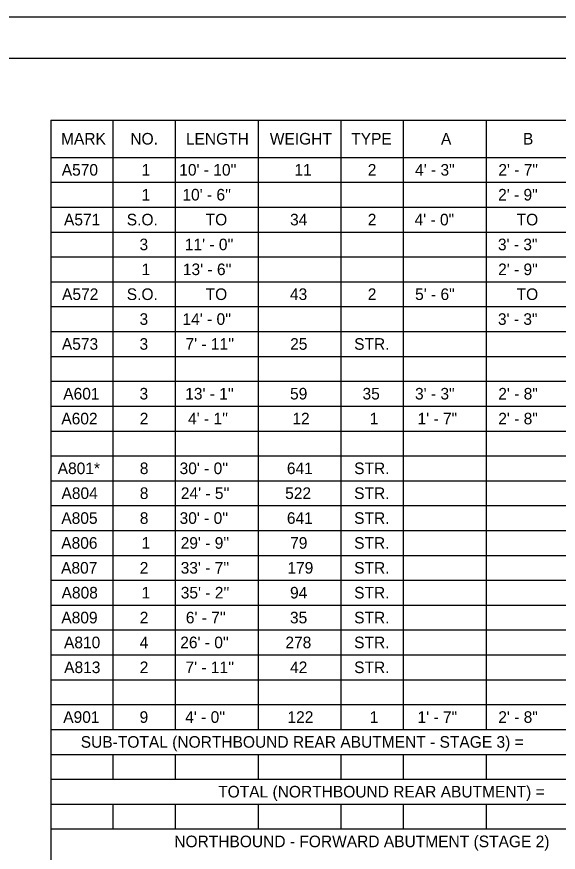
# Model space of a CAD drawing. Extents: x 1485751 to 1485785, y 230696.6 to 230718.6.
# Drawn here: x 1485773.25 to 1485779.78, y 230708.56 to 230718.64 of the extents above; entities that cross this region are included whole.
import ezdxf

# ---------------------------------------------------------------- set-up
doc = ezdxf.new("R2010")
doc.units = 0
for name, color, linetype in [('SH_Border', 7, 'Continuous'), ('SH_Cut_Line', 7, 'Continuous'), ('TX_P_Misc', 7, 'Continuous')]:
    doc.layers.add(name, color=color, linetype=linetype)

msp = doc.modelspace()

# ---------------------------------------------------------------- linework, layer by layer
at = {"layer": 'SH_Border'}
msp.add_lwpolyline([(1485753.033, 230718.141), (1485784.533, 230718.141), (1485784.533, 230697.141), (1485753.033, 230697.141)], close=True, dxfattribs=at)
at = {"layer": 'SH_Cut_Line'}
msp.add_lwpolyline([(1485751.033, 230718.641), (1485785.033, 230718.641), (1485785.033, 230696.641), (1485751.033, 230696.641)], close=True, dxfattribs=at)
at = {"layer": 'TX_P_Misc'}
for p, q in [((1485773.658, 230717.394), (1485782.908, 230717.394)), ((1485773.658, 230717.394), (1485773.658, 230699.244)), ((1485774.408, 230717.394), (1485774.408, 230710.044)), ((1485775.158, 230717.394), (1485775.158, 230710.044)), ((1485776.158, 230717.394), (1485776.158, 230710.044)), ((1485777.158, 230717.394), (1485777.158, 230710.044)), ((1485777.908, 230717.394), (1485777.908, 230710.044)), ((1485778.908, 230717.394), (1485778.908, 230710.044)), ((1485773.658, 230716.944), (1485782.908, 230716.944)), ((1485773.658, 230716.644), (1485782.908, 230716.644)), ((1485773.658, 230716.344), (1485782.908, 230716.344)), ((1485773.658, 230716.044), (1485782.908, 230716.044)), ((1485773.658, 230715.744), (1485782.908, 230715.744)), ((1485773.658, 230715.444), (1485782.908, 230715.444)), ((1485773.658, 230715.144), (1485782.908, 230715.144)), ((1485773.658, 230714.844), (1485782.908, 230714.844)), ((1485773.658, 230714.544), (1485782.908, 230714.544)), ((1485773.658, 230714.244), (1485782.908, 230714.244)), ((1485773.658, 230713.944), (1485782.908, 230713.944)), ((1485773.658, 230713.644), (1485782.908, 230713.644)), ((1485773.658, 230713.344), (1485782.908, 230713.344)), ((1485773.658, 230713.044), (1485782.908, 230713.044)), ((1485773.658, 230712.744), (1485782.908, 230712.744)), ((1485773.658, 230712.444), (1485782.908, 230712.444)), ((1485773.658, 230712.144), (1485782.908, 230712.144)), ((1485773.658, 230711.844), (1485782.908, 230711.844)), ((1485773.658, 230711.544), (1485782.908, 230711.544)), ((1485773.658, 230711.244), (1485782.908, 230711.244)), ((1485773.658, 230710.944), (1485782.908, 230710.944)), ((1485773.658, 230710.644), (1485782.908, 230710.644)), ((1485773.658, 230710.344), (1485782.908, 230710.344)), ((1485773.658, 230710.044), (1485782.908, 230710.044)), ((1485773.658, 230709.744), (1485782.908, 230709.744)), ((1485774.408, 230709.744), (1485774.408, 230709.444)), ((1485775.158, 230709.744), (1485775.158, 230709.444)), ((1485776.158, 230709.744), (1485776.158, 230709.444)), ((1485777.158, 230709.744), (1485777.158, 230709.444)), ((1485777.908, 230709.744), (1485777.908, 230709.444)), ((1485778.908, 230709.744), (1485778.908, 230709.444)), ((1485773.658, 230709.444), (1485782.908, 230709.444)), ((1485773.658, 230709.144), (1485782.908, 230709.144)), ((1485774.408, 230709.144), (1485774.408, 230708.844)), ((1485775.158, 230709.144), (1485775.158, 230708.844)), ((1485776.158, 230709.144), (1485776.158, 230708.844)), ((1485777.158, 230709.144), (1485777.158, 230708.844)), ((1485777.908, 230709.144), (1485777.908, 230708.844)), ((1485778.908, 230709.144), (1485778.908, 230708.844)), ((1485773.658, 230708.844), (1485782.908, 230708.844))]:
    msp.add_line(p, q, dxfattribs=at)

# ---------------------------------------------------------------- texts
for s, p in [('MARK', (1485773.782, 230717.099)), ('NO.', (1485774.618, 230717.099)), ('LENGTH', (1485775.288, 230717.099)), ('WEIGHT', (1485776.3, 230717.099)), ('TYPE', (1485777.282, 230717.099)), ('A', (1485778.364, 230717.099)), ('B', (1485779.353, 230717.099)), ('A570', (1485773.791, 230716.724)), ('1', (1485774.754, 230716.724)), ("10' - 10''", (1485775.208, 230716.724)), ('11', (1485776.596, 230716.724)), ('2', (1485777.481, 230716.724)), ('4\' - 3"', (1485778.052, 230716.724)), ('2\' - 7"', (1485779.056, 230716.724)), ('1', (1485774.754, 230716.424)), ("10' - 6''", (1485775.246, 230716.424)), ('2\' - 9"', (1485779.053, 230716.424)), ('A571', (1485773.818, 230716.124)), ('S.O.', (1485774.575, 230716.124)), ('TO', (1485775.526, 230716.124)), ('34', (1485776.544, 230716.124)), ('2', (1485777.481, 230716.124)), ('4\' - 0"', (1485778.046, 230716.124)), ('TO', (1485779.276, 230716.124)), ('3', (1485774.729, 230715.824)), ("11' - 0''", (1485775.275, 230715.824)), ('3\' - 3"', (1485779.051, 230715.824)), ('1', (1485774.754, 230715.524)), ("13' - 6''", (1485775.252, 230715.524)), ('2\' - 9"', (1485779.053, 230715.524)), ('A572', (1485773.795, 230715.224)), ('S.O.', (1485774.575, 230715.224)), ('TO', (1485775.526, 230715.224)), ('43', (1485776.543, 230715.224)), ('2', (1485777.481, 230715.224)), ('5\' - 6"', (1485778.052, 230715.224)), ('TO', (1485779.276, 230715.224)), ('3', (1485774.729, 230714.924)), ("14' - 0''", (1485775.247, 230714.924)), ('3\' - 3"', (1485779.051, 230714.924)), ('A573', (1485773.793, 230714.624)), ('3', (1485774.729, 230714.624)), ("7' - 11''", (1485775.283, 230714.624)), ('25', (1485776.545, 230714.624)), ('STR.', (1485777.317, 230714.624)), ('A601', (1485773.809, 230714.024)), ('3', (1485774.729, 230714.024)), ("13' - 1''", (1485775.28, 230714.024)), ('59', (1485776.544, 230714.024)), ('35', (1485777.418, 230714.024)), ('3\' - 3"', (1485778.051, 230714.024)), ('2\' - 8"', (1485779.055, 230714.024)), ('A602', (1485773.786, 230713.724)), ('2', (1485774.731, 230713.724)), ("4' - 1''", (1485775.314, 230713.724)), ('12', (1485776.572, 230713.724)), ('1', (1485777.504, 230713.724)), ('1\' - 7"', (1485778.082, 230713.724)), ('2\' - 8"', (1485779.055, 230713.724)), ('A801*', (1485773.742, 230713.124)), ('8', (1485774.732, 230713.124)), ("30' - 0''", (1485775.212, 230713.124)), ('641', (1485776.506, 230713.124)), ('STR.', (1485777.317, 230713.124)), ('A804', (1485773.788, 230712.824)), ('8', (1485774.732, 230712.824)), ("24' - 5''", (1485775.227, 230712.824)), ('522', (1485776.485, 230712.824)), ('STR.', (1485777.317, 230712.824)), ('A805', (1485773.786, 230712.524)), ('8', (1485774.732, 230712.524)), ("30' - 0''", (1485775.212, 230712.524)), ('641', (1485776.506, 230712.524)), ('STR.', (1485777.317, 230712.524)), ('A806', (1485773.785, 230712.224)), ('1', (1485774.754, 230712.224)), ("29' - 9''", (1485775.225, 230712.224)), ('79', (1485776.545, 230712.224)), ('STR.', (1485777.317, 230712.224)), ('A807', (1485773.783, 230711.924)), ('2', (1485774.731, 230711.924)), ("33' - 7''", (1485775.225, 230711.924)), ('179', (1485776.512, 230711.924)), ('STR.', (1485777.317, 230711.924)), ('A808', (1485773.789, 230711.624)), ('1', (1485774.754, 230711.624)), ("35' - 2''", (1485775.226, 230711.624)), ('94', (1485776.544, 230711.624)), ('STR.', (1485777.317, 230711.624)), ('A809', (1485773.786, 230711.324)), ('2', (1485774.731, 230711.324)), ("6' - 7''", (1485775.287, 230711.324)), ('35', (1485776.543, 230711.324)), ('STR.', (1485777.317, 230711.324)), ('A810', (1485773.818, 230711.024)), ('4', (1485774.731, 230711.024)), ("26' - 0''", (1485775.22, 230711.024)), ('278', (1485776.488, 230711.024)), ('STR.', (1485777.317, 230711.024)), ('A813', (1485773.82, 230710.724)), ('2', (1485774.731, 230710.724)), ("7' - 11''", (1485775.283, 230710.724)), ('42', (1485776.544, 230710.724)), ('STR.', (1485777.317, 230710.724)), ('A901', (1485773.809, 230710.124)), ('9', (1485774.73, 230710.124)), ("4' - 0''", (1485775.28, 230710.124)), ('122', (1485776.513, 230710.124)), ('1', (1485777.504, 230710.124)), ('1\' - 7"', (1485778.082, 230710.124)), ('2\' - 8"', (1485779.055, 230710.124)), ('SUB-TOTAL (NORTHBOUND REAR ABUTMENT - STAGE 3) =', (1485774.02, 230709.824)), ('TOTAL (NORTHBOUND REAR ABUTMENT) =', (1485775.677, 230709.224)), ('NORTHBOUND - FORWARD ABUTMENT (STAGE 2)', (1485775.148, 230708.624))]:
    msp.add_text(s, height=0.14, dxfattribs=at).set_placement(p)

doc.saveas('drawing.dxf')
